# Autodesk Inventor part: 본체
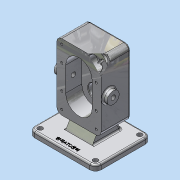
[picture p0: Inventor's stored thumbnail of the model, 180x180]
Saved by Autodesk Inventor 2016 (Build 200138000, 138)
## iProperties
Created: 2020-04
Part Number: 본체
Material: 알루미늄 6061
Document SubType Name: Modeling
Designer: Administrator
Density: 2.7 g/cm^3
Appearance: 알루미늄 - 평지
Mass: 1471.87 g
Surface Area: 820.773 cm^2
Volume: 545.135 cm^3
Author: Administrator
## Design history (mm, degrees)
sketch "스케치1"
  geometry: L1 (60, -50)-(-60, -50); L2 (-60, -50)-(-60, 50); L3 (-60, 50)-(60, 50); L4 (60, 50)-(60, -50); L5 (60, -50)-(-60, 50); L6 (-60, -50)-(60, 50); 1 further point
  constraints: 12 end point, 2 midpoint, 2 parallel, 1 horizontal, 1 perpendicular
  dimensions: "d0" = 120 distance of L2.end L3.end; "d1" = 100 distance of L1.end L2.end
extrude "돌출1" new body sketch "스케치1" distance "d2" = 10; taper "d3" = 0 deg
sketch "스케치3"
  geometry: L1 (-20, 150)-(33, 150); L2 (33, 150)-(33, 30); L3 (33, 30)-(-20, 30); L4 (-20, 30)-(-20, 150); L5 (-50, 0)-(50, 0) reference; L6 (50, 0)-(50, 10) reference; 1 further point
  constraints: 8 end point, 2 parallel, 1 horizontal, 1 perpendicular
  dimensions: "d7" = 150 distance between parallel lines of L5 L1; "d8" = 17 distance between parallel lines of L6 L2; "d9" = 53 distance of L1.start L1.end; "d10" = 120 distance between parallel lines of L3 L1
extrude "돌출2" join sketch "스케치3" stored distance "d11" = 80; taper "d12" = 0 deg
sketch "스케치4"
  geometry: 1 further point
sketch "스케치5"
  geometry: L1 (50, 10)-(-50, 10) reference; L2 (33, 10)-(18.227, 35.588); L3 (-20, 10)-(-4.793, 36.339); L4 (50, 0)-(50, 10) reference; 1 further point
  constraints: 4 end point, 2 point on line
  dimensions: "d13" = 17 distance from line of L4 L2.start; "d14" = 53 distance of L2.start L3.start; "d15" = 60 deg angle of L1 L3; "d16" = 60 deg angle of L1 L2
feature "리브1" sketch "스케치5" dims "d17" = 1, "d18" = 48, "d19" = 0, "d20" = 0, "d21" = 1, "d22" = 1
sketch "스케치6"
  geometry: L1 (40, -82)-(40, -38); L2 (16, -82)-(16, -38); L3 (64, -38)-(64, -82); L4 (0, -120)-(0, 0) reference; L5 (0, 0)-(80, 0) reference; A1 r 24 centre (40, -82) between (16, -82) and (64, -82); A2 r 24 centre (40, -38) between (64, -38) and (16, -38); 5 further points
  constraints: 8 end point, 4 midpoint, 4 point on circle, 4 tangent, 2 centre point, 1 horizontal alignment, 1 parallel, 1 vertical, 1 vertical alignment
  dimensions: "d23" = 24 radius of A2; "d24" = 92 dimension on A1 A2
extrude "돌출3" cut sketch "스케치6" distance "d25" = 29; taper "d26" = 0 deg
sketch "스케치7"
  geometry: C1 r 12.5 at (40, -38); C2 r 12.5 at (40, -82); A1 r 24 centre (40, -38) between (64, -38) and (16, -38) reference; A2 r 24 centre (40, -82) between (16, -82) and (64, -82) reference; 1 further point
  constraints: 2 centre point, 2 concentric
  dimensions: "d27" = 25 diameter of C1; "d28" = 25 diameter of C2
extrude "돌출4" cut sketch "스케치7" distance "d29" = 15; taper "d30" = 0 deg
sketch "스케치8"
  geometry: C1 r 19 at (40, 38); C2 r 12.5 at (40, 38) reference; 1 further point
  constraints: 1 centre point, 1 concentric
  dimensions: "d31" = 38 diameter of C1
extrude "돌출5" join sketch "스케치8" distance "d32" = 17; taper "d33" = 0 deg
sketch "스케치9"
  geometry: C1 r 8.5 at (0, 0); C2 r 12.5 at (0, 0) reference; 1 further point
  constraints: 1 centre point, 1 concentric
  dimensions: "d34" = 17 diameter of C1
extrude "돌출6" cut sketch "스케치9" stored distance "d35" = 17; taper "d36" = 0 deg
sketch "스케치10"
  geometry: C1 r 14 at (0, 0); C2 r 19 at (0, 0) reference; 1 further point
  constraints: 1 centre point, 1 concentric
  dimensions: "d37" = 28 diameter of C1
extrude "돌출7" cut sketch "스케치10" distance "d38" = 7.3; taper "d39" = 0 deg
sketch "스케치11"
  geometry: L1 (80, 0)-(0, 0) reference; L2 (40, 0)-(40, -120); L3 (80, -120)-(0, -120) reference; L4 (0, 0)-(0, -120) reference; L5 (0, -60)-(80, -60); L6 (80, 0)-(80, -120) reference; 9 further points
  constraints: 6 symmetric about line, 4 end point, 4 midpoint, 1 vertical alignment
  dimensions: "d40" = 62 distance of point (71, -9) point (9, -9); "d41" = 102 distance of point (9, -111) point (9, -9); "d42" = 29 distance of point (9, -38) point (9, -9)
hole "구멍1" sketch "스케치11" at (9, -9), (71, -9), (71, -38), (9, -38), (9, -82), (71, -82), (71, -111), (9, -111) diameter "d43" = 4.134; stored, may be unused: countersink angle "d47" = 90 deg, drill point angle "d49" = 118 deg; dims "d44" = 10, "d45" = 4, "d46" = 2, "d48" = 12
sketch "스케치12"
  geometry: L1 (-150, -20)-(-30, -20) reference; C1 r 11 at (-90, -6); 2 further points
  constraints: 1 centre point, 1 midpoint, 1 vertical alignment
  dimensions: "d50" = 22 diameter of C1; "d51" = 14 distance of point (-90, -20) C1.centre
extrude "돌출8" join sketch "스케치12" distance "d52" = 8; taper "d53" = 0 deg
hole "구멍2" diameter "d56" = 8.376; stored, may be unused: countersink angle "d60" = 90 deg, drill point angle "d62" = 118 deg; dims "d57" = 20, "d58" = 4, "d59" = 2, "d61" = 27.3, "d72" = 10, "d73" = 10
hole "구멍3" diameter "d65" = 8.376; stored, may be unused: countersink angle "d69" = 90 deg, drill point angle "d71" = 118 deg; dims "d66" = 20, "d67" = 4, "d68" = 2, "d70" = 27.3, "d74" = 10, "d75" = 10
fillet "모깎기1" dims "d76" = 10
hole "구멍4" diameter "d79" = 9; stored, may be unused: countersink angle "d83" = 90 deg, drill point angle "d85" = 118 deg; dims "d77" = 10, "d78" = 10, "d80" = 20, "d81" = 4, "d82" = 2, "d84" = 27.3
sketch "스케치13"
  geometry: L1 (-50, -50)-(50, -50) reference; L2 (-60, 40)-(-60, -40) reference; 2 further points
  constraints: 1 other
  dimensions: "d86" = 10 distance from line of L1 point (0, -40); "d87" = 60 distance from line of L2 point (0, -40)
feature "엠보싱1" sketch "스케치13" dims "d88" = 0.5, "d89" = 0
fillet "모깎기2" dims "d90" = 9
fillet "모깎기3" dims "d91" = 0.5
chamfer "모따기1" distance "d92" = 0.7; stored, may be unused: second distance "d93" = 2, angle "d94" = 30 deg
fillet "모깎기4" dims "d95" = 3
fillet "모깎기5" dims "d96" = 3
chamfer "모따기2" distance "d97" = 1; stored, may be unused: second distance "d98" = 2, angle "d99" = 60 deg
fillet "모깎기6" dims "d100" = 3
fillet "모깎기7" dims "d101" = 3
feature "분할1"
node "솔리드1"
mirror "대칭1"
mirror "대칭2"
mirror "대칭3"
